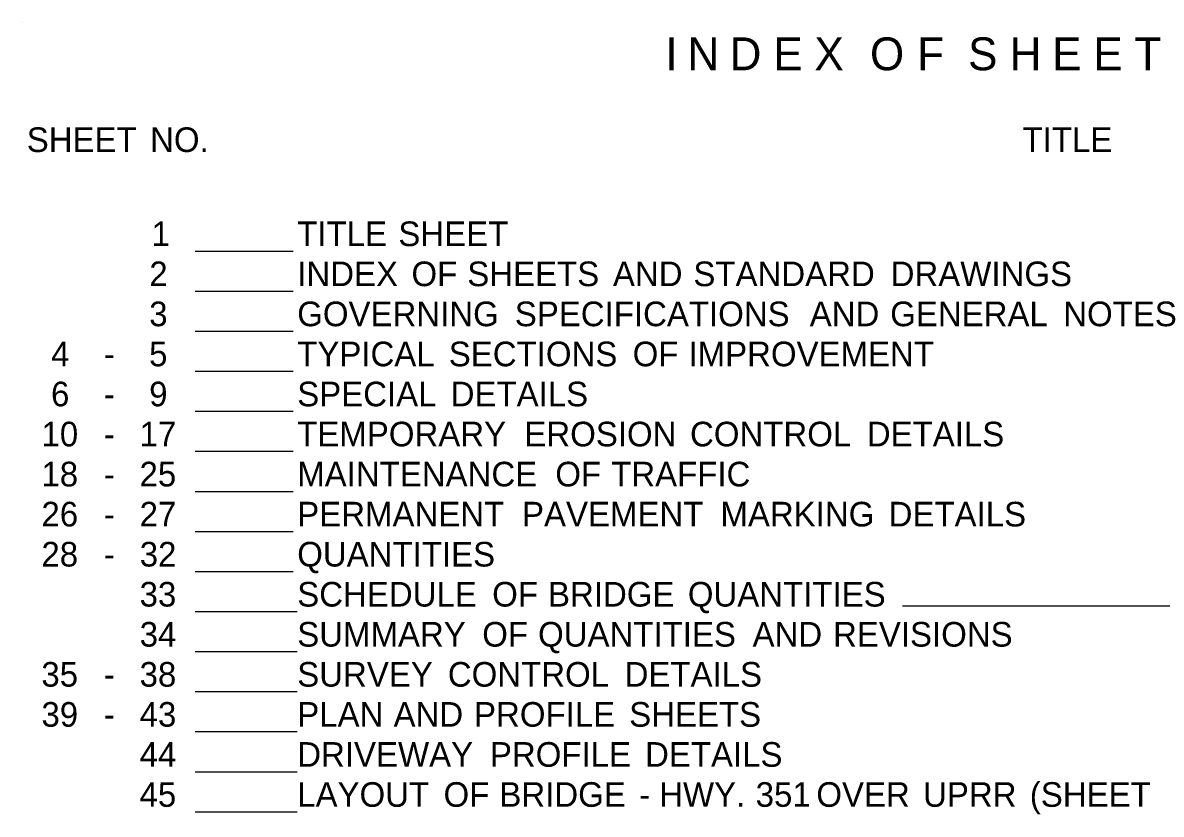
# Model space of a CAD drawing. Extents: x 2 to 32.9, y 0.7 to 21.4.
# Drawn here: x 1.98 to 9.25, y 16.32 to 21.37 of the extents above; entities that cross this region are included whole.
import ezdxf

# ---------------------------------------------------------------- set-up
doc = ezdxf.new("R2010")
doc.units = 0
doc.layers.add('Default', color=7, linetype='Continuous')

msp = doc.modelspace()

# ---------------------------------------------------------------- linework, layer by layer
at = {"layer": 'Default'}
for p, q in [((1.9832, 21.3706), (1.9832, 21.3706)), ((1.9832, 21.3706), (1.9832, 21.3706)), ((3.0822, 19.9137), (3.7084, 19.9137)), ((3.0822, 19.9137), (3.7084, 19.9137)), ((3.0822, 19.6581), (3.7084, 19.6581)), ((3.0822, 19.6581), (3.7084, 19.6581)), ((3.0822, 19.4025), (3.7084, 19.4025)), ((3.0822, 19.4025), (3.7084, 19.4025)), ((3.0822, 19.1469), (3.7084, 19.1469)), ((3.0822, 19.1469), (3.7084, 19.1469)), ((3.0822, 18.8913), (3.7084, 18.8913)), ((3.0822, 18.8913), (3.7084, 18.8913)), ((3.0822, 18.6358), (3.7084, 18.6358)), ((3.0822, 18.6358), (3.7084, 18.6358)), ((3.0822, 18.3802), (3.7084, 18.3802)), ((3.0822, 18.3802), (3.7084, 18.3802)), ((3.0822, 18.1246), (3.7084, 18.1246)), ((3.0822, 18.1246), (3.7084, 18.1246)), ((3.0822, 17.869), (3.7084, 17.869)), ((3.0822, 17.869), (3.7084, 17.869)), ((7.5944, 17.6485), (13.6355, 17.6485)), ((3.0822, 17.6134), (3.734, 17.6134)), ((3.0822, 17.6134), (3.7084, 17.6134)), ((3.0822, 17.6134), (3.7084, 17.6134)), ((3.0822, 17.3578), (3.734, 17.3578)), ((3.0822, 17.3578), (3.7084, 17.3578)), ((3.0822, 17.3578), (3.7084, 17.3578)), ((3.0822, 17.1022), (3.734, 17.1022)), ((3.0822, 17.1022), (3.7084, 17.1022)), ((3.0822, 17.1022), (3.7084, 17.1022)), ((3.0822, 16.8466), (3.734, 16.8466)), ((3.0822, 16.8466), (3.7084, 16.8466)), ((3.0822, 16.8466), (3.7084, 16.8466)), ((3.0822, 16.591), (3.734, 16.591)), ((3.0822, 16.591), (3.7084, 16.591)), ((3.0822, 16.591), (3.7084, 16.591)), ((3.0822, 16.3354), (3.734, 16.3354)), ((3.0822, 16.3354), (3.7084, 16.3354)), ((3.0822, 16.3354), (3.7084, 16.3354))]:
    msp.add_line(p, q, dxfattribs=at)

# ---------------------------------------------------------------- texts
for s, height, p in [('  O', 0.20972, (7.2317, 21.0675)), ('  O', 0.20972, (7.2317, 21.0675)), ('  S', 0.20972, (7.8575, 21.0675)), ('  S', 0.20972, (7.8575, 21.0675)), ('I', 0.2097, (6.0826, 21.0675)), ('I', 0.2097, (6.0826, 21.0675)), (' N', 0.20972, (6.1449, 21.0675)), (' N', 0.20972, (6.1449, 21.0675)), (' D', 0.20972, (6.4144, 21.0675)), (' D', 0.20972, (6.4144, 21.0675)), (' E', 0.20972, (6.6929, 21.0675)), (' E', 0.20972, (6.6929, 21.0675)), (' X', 0.20972, (6.9552, 21.0675)), (' X', 0.20972, (6.9552, 21.0675)), (' F', 0.20972, (7.6107, 21.0675)), (' F', 0.20972, (7.6107, 21.0675)), (' H', 0.20972, (8.2013, 21.0675)), (' H', 0.20972, (8.2013, 21.0675)), (' E', 0.20972, (8.4718, 21.0675)), (' E', 0.20972, (8.4718, 21.0675)), (' E', 0.20972, (8.7341, 21.0675)), (' E', 0.20972, (8.7341, 21.0675)), (' T', 0.20972, (8.9964, 21.0675)), (' T', 0.20972, (8.9964, 21.0675)), ('SHEET', 0.15729, (2.0087, 20.5458)), ('SHEET', 0.15729, (2.0087, 20.5458)), (' NO.', 0.15729, (2.737, 20.5458)), (' NO.', 0.15729, (2.737, 20.5458)), ('TITLE', 0.15729, (8.3607, 20.5458)), ('TITLE', 0.15729, (8.3607, 20.5458)), ('1', 0.1573, (2.8049, 19.9452)), ('1', 0.1573, (2.8049, 19.9452)), ('TITLE', 0.15729, (3.734, 19.9452)), ('TITLE', 0.15729, (3.734, 19.9452)), (' SHEET', 0.15729, (4.3206, 19.9452)), (' SHEET', 0.15729, (4.3206, 19.9452)), ('2', 0.1573, (2.7905, 19.6896)), ('2', 0.1573, (2.7905, 19.6896)), ('INDEX', 0.15729, (3.734, 19.6896)), ('INDEX', 0.15729, (3.734, 19.6896)), (' OF', 0.15729, (4.4042, 19.6896)), (' OF', 0.15729, (4.4042, 19.6896)), (' SHEETS', 0.15729, (4.7604, 19.6896)), (' SHEETS', 0.15729, (4.7604, 19.6896)), (' AND', 0.15729, (5.6894, 19.6896)), (' AND', 0.15729, (5.6894, 19.6896)), (' STANDARD', 0.15729, (6.2027, 19.6896)), (' STANDARD', 0.15729, (6.2027, 19.6896)), (' DRAWINGS', 0.15729, (7.461, 19.6896)), (' DRAWINGS', 0.15729, (7.461, 19.6896)), ('3', 0.1573, (2.7897, 19.434)), ('3', 0.1573, (2.7897, 19.434)), ('GOVERNING', 0.15729, (3.734, 19.434)), ('GOVERNING', 0.15729, (3.734, 19.434)), (' SPECIFICATIONS', 0.157286, (5.0635, 19.434)), (' SPECIFICATIONS', 0.157286, (5.0635, 19.434)), (' AND', 0.15729, (6.9448, 19.434)), (' AND', 0.15729, (6.9448, 19.434)), (' GENERAL', 0.15729, (7.4581, 19.434)), (' GENERAL', 0.15729, (7.4581, 19.434)), (' NOTES', 0.15729, (8.5618, 19.434)), (' NOTES', 0.15729, (8.5618, 19.434)), ('4', 0.1573, (2.1638, 19.1784)), ('4', 0.1573, (2.1638, 19.1784)), ('5', 0.1573, (2.7891, 19.1784)), ('5', 0.1573, (2.7891, 19.1784)), ('TYPICAL', 0.15729, (3.734, 19.1784)), ('TYPICAL', 0.15729, (3.734, 19.1784)), (' SECTIONS', 0.15729, (4.6422, 19.1784)), (' SECTIONS', 0.15729, (4.6422, 19.1784)), (' OF', 0.15729, (5.8153, 19.1784)), (' OF', 0.15729, (5.8153, 19.1784)), (' IMPROVEMENT', 0.157286, (6.1714, 19.1784)), (' IMPROVEMENT', 0.157286, (6.1714, 19.1784)), ('-', 0.1573, (2.4995, 19.1784)), ('-', 0.1573, (2.4995, 19.1784)), ('6', 0.1573, (2.1635, 18.9228)), ('6', 0.1573, (2.1635, 18.9228)), ('9', 0.1573, (2.7896, 18.9228)), ('9', 0.1573, (2.7896, 18.9228)), ('SPECIAL', 0.15729, (3.734, 18.9228)), ('SPECIAL', 0.15729, (3.734, 18.9228)), (' DETAILS', 0.15729, (4.6545, 18.9228)), (' DETAILS', 0.15729, (4.6545, 18.9228)), ('-', 0.1573, (2.4995, 18.9228)), ('-', 0.1573, (2.4995, 18.9228)), ('10', 0.15729, (2.1027, 18.6672)), ('10', 0.15729, (2.1027, 18.6672)), ('17', 0.15729, (2.7286, 18.6672)), ('17', 0.15729, (2.7286, 18.6672)), ('TEMPORARY', 0.15729, (3.734, 18.6672)), ('TEMPORARY', 0.15729, (3.734, 18.6672)), (' EROSION', 0.15729, (5.1245, 18.6672)), (' EROSION', 0.15729, (5.1245, 18.6672)), (' CONTROL', 0.15729, (6.1811, 18.6672)), (' CONTROL', 0.15729, (6.1811, 18.6672)), (' DETAILS', 0.15729, (7.3089, 18.6672)), (' DETAILS', 0.15729, (7.3089, 18.6672)), ('-', 0.1573, (2.4995, 18.6672)), ('-', 0.1573, (2.4995, 18.6672)), ('18', 0.15729, (2.1023, 18.4116)), ('18', 0.15729, (2.1023, 18.4116)), ('25', 0.15729, (2.728, 18.4116)), ('25', 0.15729, (2.728, 18.4116)), ('MAINTENANCE', 0.157286, (3.734, 18.4116)), ('MAINTENANCE', 0.157286, (3.734, 18.4116)), (' OF', 0.15729, (5.3219, 18.4116)), (' OF', 0.15729, (5.3219, 18.4116)), (' TRAFFIC', 0.15729, (5.6781, 18.4116)), (' TRAFFIC', 0.15729, (5.6781, 18.4116)), ('-', 0.1573, (2.4995, 18.4116)), ('-', 0.1573, (2.4995, 18.4116)), ('26', 0.15729, (2.1024, 18.156)), ('26', 0.15729, (2.1024, 18.156)), ('27', 0.15729, (2.7286, 18.156)), ('27', 0.15729, (2.7286, 18.156)), ('PERMANENT', 0.15729, (3.734, 18.156)), ('PERMANENT', 0.15729, (3.734, 18.156)), (' PAVEMENT', 0.15729, (5.1095, 18.156)), (' PAVEMENT', 0.15729, (5.1095, 18.156)), (' MARKING', 0.15729, (6.3752, 18.156)), (' MARKING', 0.15729, (6.3752, 18.156)), (' DETAILS', 0.15729, (7.4482, 18.156)), (' DETAILS', 0.15729, (7.4482, 18.156)), ('-', 0.1573, (2.4995, 18.156)), ('-', 0.1573, (2.4995, 18.156)), ('28', 0.15729, (2.1023, 17.9004)), ('28', 0.15729, (2.1023, 17.9004)), ('32', 0.15729, (2.7294, 17.9004)), ('32', 0.15729, (2.7294, 17.9004)), ('QUANTITIES', 0.15729, (3.734, 17.9004)), ('QUANTITIES', 0.15729, (3.734, 17.9004)), ('-', 0.1573, (2.4995, 17.9004)), ('-', 0.1573, (2.4995, 17.9004)), ('33', 0.15729, (2.7286, 17.6449)), ('33', 0.15729, (2.7286, 17.6449)), ('SCHEDULE', 0.15729, (3.734, 17.6449)), ('SCHEDULE', 0.15729, (3.734, 17.6449)), (' OF', 0.15729, (4.9191, 17.6449)), (' OF', 0.15729, (4.9191, 17.6449)), (' BRIDGE', 0.15729, (5.2753, 17.6449)), (' BRIDGE', 0.15729, (5.2753, 17.6449)), (' QUANTITIES', 0.157286, (6.1672, 17.6449)), (' QUANTITIES', 0.157286, (6.1672, 17.6449)), ('34', 0.15729, (2.729, 17.3893)), ('34', 0.15729, (2.729, 17.3893)), ('SUMMARY', 0.15729, (3.734, 17.3893)), ('SUMMARY', 0.15729, (3.734, 17.3893)), (' OF', 0.15729, (4.8557, 17.3893)), (' OF', 0.15729, (4.8557, 17.3893)), (' QUANTITIES', 0.157286, (5.2119, 17.3893)), (' QUANTITIES', 0.157286, (5.2119, 17.3893)), (' AND', 0.15729, (6.5802, 17.3893)), (' AND', 0.15729, (6.5802, 17.3893)), (' REVISIONS', 0.15729, (7.0936, 17.3893)), (' REVISIONS', 0.15729, (7.0936, 17.3893)), ('35', 0.15729, (2.1018, 17.1337)), ('35', 0.15729, (2.1018, 17.1337)), ('38', 0.15729, (2.7285, 17.1337)), ('38', 0.15729, (2.7285, 17.1337)), ('SURVEY', 0.15729, (3.734, 17.1337)), ('SURVEY', 0.15729, (3.734, 17.1337)), (' CONTROL', 0.15729, (4.6362, 17.1337)), (' CONTROL', 0.15729, (4.6362, 17.1337)), (' DETAILS', 0.15729, (5.7639, 17.1337)), (' DETAILS', 0.15729, (5.7639, 17.1337)), ('-', 0.1573, (2.4995, 17.1337)), ('-', 0.1573, (2.4995, 17.1337)), ('39', 0.15729, (2.1023, 16.8781)), ('39', 0.15729, (2.1023, 16.8781)), ('43', 0.15729, (2.7286, 16.8781)), ('43', 0.15729, (2.7286, 16.8781)), ('PLAN', 0.15729, (3.734, 16.8781)), ('PLAN', 0.15729, (3.734, 16.8781)), (' AND', 0.15729, (4.2901, 16.8781)), (' AND', 0.15729, (4.2901, 16.8781)), (' PROFILE', 0.15729, (4.8034, 16.8781)), (' PROFILE', 0.15729, (4.8034, 16.8781)), (' SHEETS', 0.15729, (5.7931, 16.8781)), (' SHEETS', 0.15729, (5.7931, 16.8781)), ('-', 0.1573, (2.4995, 16.8781)), ('-', 0.1573, (2.4995, 16.8781)), ('44', 0.15729, (2.729, 16.6225)), ('44', 0.15729, (2.729, 16.6225)), ('DRIVEWAY', 0.15729, (3.734, 16.6225)), ('DRIVEWAY', 0.15729, (3.734, 16.6225)), (' PROFILE', 0.15729, (4.9046, 16.6225)), (' PROFILE', 0.15729, (4.9046, 16.6225)), (' DETAILS', 0.15729, (5.8943, 16.6225)), (' DETAILS', 0.15729, (5.8943, 16.6225)), ('45', 0.15729, (2.728, 16.3669)), ('45', 0.15729, (2.728, 16.3669)), ('LAYOUT', 0.15729, (3.734, 16.3669)), ('LAYOUT', 0.15729, (3.734, 16.3669)), (' OF', 0.15729, (4.6089, 16.3669)), (' OF', 0.15729, (4.6089, 16.3669)), (' BRIDGE', 0.15729, (4.965, 16.3669)), (' BRIDGE', 0.15729, (4.965, 16.3669)), (' HWY.', 0.15729, (5.9843, 16.3669)), (' HWY.', 0.15729, (5.9843, 16.3669)), (' 351', 0.15729, (6.5999, 16.3669)), (' 351', 0.15729, (6.5999, 16.3669)), (' OVER', 0.15729, (6.987, 16.3669)), (' OVER', 0.15729, (6.987, 16.3669)), (' UPRR', 0.15729, (7.6679, 16.3669)), (' UPRR', 0.15729, (7.6679, 16.3669)), (' (SHEET', 0.15729, (8.3487, 16.3669)), (' (SHEET', 0.15729, (8.3487, 16.3669)), (' -', 0.15729, (5.857, 16.3669)), (' -', 0.15729, (5.857, 16.3669))]:
    msp.add_text(s, height=height, dxfattribs=at).set_placement(p)

doc.saveas('drawing.dxf')
